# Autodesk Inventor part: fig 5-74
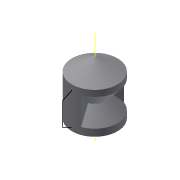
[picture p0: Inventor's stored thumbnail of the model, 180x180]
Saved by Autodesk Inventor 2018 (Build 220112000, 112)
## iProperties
Created: 2004-05
Part Number: fig 5-74
Document SubType Name: Modeling
Designer: CADCIM Technologies
Manufacturer: Standard
Standards Organization: Custom
Density: 1 g/cm^3
Material: Generic
Appearance: Default
Author: CADCIM Technologies
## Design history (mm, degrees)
sketch "Sketch1"
  geometry: L1 (0, -21.51)-(0, 21.51); L2 (0, 21.51)-(-14.639, 13.059); L3 (-14.639, 13.059)-(-14.639, -13.059); L4 (-14.639, -13.059)-(0, -21.51); 2 further points
  constraints: 8 end point, 1 coincident, 1 equal length, 1 midpoint, 1 parallel, 1 vertical, 1 other
  dimensions: "d3" = 120 deg angle of L4 L3
revolve "Revolution1" sketch "Sketch1" stored, may be unused: angle "d0" = 90 deg
workaxis "Work Axis1"
sketch "Sketch2"
  geometry: L1 (-15.658, 10.423)-(-7.144, 0); L2 (-7.144, 0)-(-15.658, -9.738); L3 (-15.658, -9.738)-(-15.658, 10.423); L4 (0, -25.812)-(0, 34.416) reference
  constraints: 6 end point, 1 vertical
revolve "Revolution2" sketch "Sketch2" stored, may be unused: angle "d4" = 140 deg
sketch "Sketch3"
  geometry: L1 (-14.955, 9.983)-(-20.736, 7.191); L2 (-20.736, 7.191)-(-20.736, -7.686); L3 (-20.736, -7.686)-(-15, -10.57); L4 (0, -25.812)-(0, 34.416) reference
  constraints: 6 end point, 1 equal length, 1 vertical
body "Solid1"
